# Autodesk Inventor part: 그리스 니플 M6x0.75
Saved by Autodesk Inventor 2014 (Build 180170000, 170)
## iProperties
Created: 2025-10
Part Number: 그리스 니플 M6x0.75
Material: 일반
Document SubType Name: Modeling
Designer: dg
Density: 1 g/cm^3
Appearance: 기본값
Author: dg
Author: jhkim
Description: 윤활 니플, 원추 유형 A
Creation Date: 2025-10-01
Sending System: Autodesk Inventor 2026
Preprocessor: ST-DEVELOPER v20.1
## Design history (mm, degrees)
node "그리스 니플 M6x0.751"
body "Solid1"
node "기준1"
